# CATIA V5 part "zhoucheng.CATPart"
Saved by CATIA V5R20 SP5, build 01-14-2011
Part number: 3.29
Bounding box of the stored display mesh (mm): x -100 to 100, y -99.999 to 99.999, z -2.5 to 24.281
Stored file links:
  E:\180522132\轴承\zhoucheng.CATPart
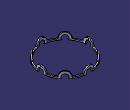
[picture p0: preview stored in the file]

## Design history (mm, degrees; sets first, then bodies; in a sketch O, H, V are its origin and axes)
Body1 (main body)
  Sketch1 on xy-plane, origin (0, 0, 0), H (1, 0, 0), V (0, 1, 0)
    circle A1 centre (0, 0) radius 100
    radius A1 = 100
  Pad1: profile Sketch1, direction (0, 0, 1), length 2.5, mirrored extent, thin wall 5
  Body2
    Sketch2 on end face of Pad1, origin (0, 0, 2.5), H (1, 0, 0), V (0, 1, 0)
      arc A1 centre (99.2818, 0) radius 20 from (97.4988, -19.9204) to (97.4988, 19.9204) ccw
      point P1 (99.2818, 0)
      construction line L1 (97.4988, 0.4868) -> (97.4988, 42.2673)
      point P2 (97.4988, 0.4868)
      axis line L2 (97.4988, 42.2673) -> (97.4988, -52.6282)
      point P5 (97.4988, 19.9204)
      point P6 (97.4988, -19.9204)
      radius A1 = 20
      distance O P2 = 97.5
      coincidence: P1 H, L1 P5, L2 P6
      vertical: L1 V, L2 V
    Shaft1: profile Sketch2, axis Sketch2.L2, angle 360
    CircPattern1: of Shaft1, instances 8, angular step 45, axis from end face of Pad1
    Sketch3 on end face of Pad1, origin (0, 0, 2.5), H (1, 0, 0), V (0, 1, 0)
      circle A1 centre (0, 0) radius 95
      radius A1 = 95
    Pocket1: profile Sketch3, direction (0, 0, -1), length 60, mirrored extent
    Sketch4 on xy-plane, origin (0, 0, 0), H (1, 0, 0), V (0, 1, 0)
      circle A1 centre (0, 0) radius 119.6177
    Pocket2: profile Sketch4, direction (0, 0, -1), length 60
    Sketch5 on end face of Pad1, origin (0, 0, 2.5), H (1, 0, 0), V (0, 1, 0)
      circle A1 centre (0, 0) radius 100
      radius A1 = 100
    Pocket3: profile Sketch5, direction (0, 0, -1), length 60, mirrored extent, outer side
  Assemble1: tool Body2
  Body3
    Plane1: type Offset, RefPlane yz-plane, Offset 97.5
    Sketch6 on Plane1, origin (97.5, 0, 0), H (0, 1, 0), V (0, 0, 1)
      arc A1 centre (0, 3.842) radius 12 from (10.1744, -2.5205) to (-10.1744, -2.5205) ccw
      point P1 (0, 3.842)
      axis line L1 (-60.1495, -2.5205) -> (33.4828, -2.5205)
      point P4 (-10.1744, -2.5205)
      point P5 (10.1744, -2.5205)
      radius A1 = 12
      coincidence: P1 V, L1 P4, L1 P5
      horizontal: L1 H
    Shaft2: profile Sketch6, axis Sketch6.L1, angle 360
    CircPattern2: of the body so far, instances 8, angular step 45, axis from face of Pad1
  Remove1: tool Body3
